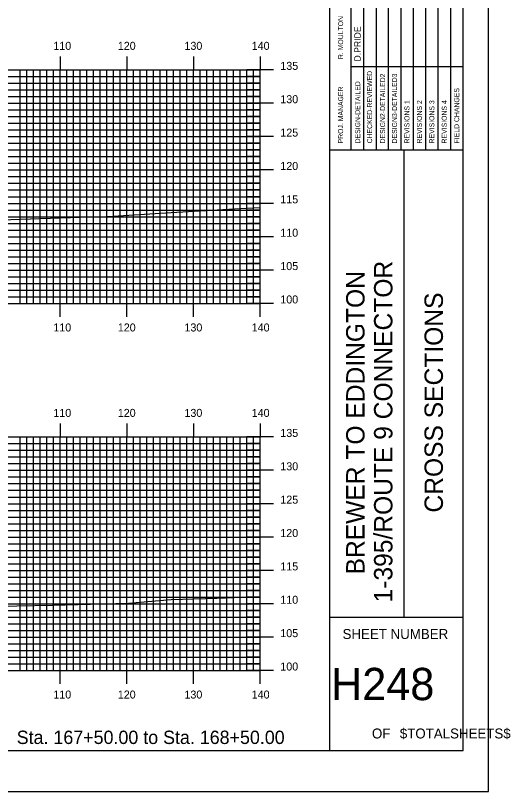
# Model space of a CAD drawing. Extents: x 1781860 to 1782203, y 442591 to 442811.
# Drawn here: x 1782129.2 to 1782203.4, y 442590.5 to 442706.8 of the extents above; entities that cross this region are included whole.
import ezdxf

# ---------------------------------------------------------------- set-up
doc = ezdxf.new("R2010")
doc.units = 0
for name, color, linetype in [('BORDER', 7, 'Continuous'), ('H_V ANNOTATION', 7, 'Continuous'), ('MAJOR', 7, 'Continuous'), ('MINOR', 7, 'Continuous'), ('PLOT BOUNDARY', 7, 'Continuous'), ('S_Roadway_Centerline', 7, 'Continuous')]:
    doc.layers.add(name, color=color, linetype=linetype)

msp = doc.modelspace()

# ---------------------------------------------------------------- linework, layer by layer
at = {"layer": 'BORDER'}
for p, q in [((1782176.32, 442596.67), (1782176.32, 442806.67)), ((1782176.32, 442686.67), (1782196.32, 442686.67)), ((1782187.5, 442616.67), (1782187.5, 442686.67)), ((1782176.32, 442616.67), (1782196.32, 442616.67))]:
    msp.add_line(p, q, dxfattribs=at)
msp.add_lwpolyline([(1781876.32, 442596.67), (1782196.32, 442596.67), (1782196.32, 442806.67), (1781876.32, 442806.67)], close=True, dxfattribs=at)
for points in [[(1782181.42, 442686.68), (1782181.42, 442721.67)], [(1782183.28, 442721.67), (1782183.28, 442686.68)], [(1782185.14, 442686.68), (1782185.14, 442721.67)], [(1782187.01, 442686.68), (1782187.01, 442721.67)], [(1782188.87, 442686.68), (1782188.87, 442721.67)], [(1782190.73, 442686.68), (1782190.73, 442721.67)], [(1782192.6, 442686.68), (1782192.6, 442721.67)], [(1782194.46, 442686.68), (1782194.46, 442721.67)], [(1782179.55, 442686.68), (1782179.55, 442720.26)], [(1782179.55, 442699.17), (1782196.32, 442699.17)]]:
    msp.add_lwpolyline(points, dxfattribs=at)
at = {"layer": 'MAJOR'}
for p, q in [((1782135.92, 442700.67), (1782135.92, 442698.67)), ((1782145.92, 442700.67), (1782145.92, 442698.67)), ((1782155.92, 442700.67), (1782155.92, 442698.67)), ((1782165.92, 442700.67), (1782165.92, 442698.67)), ((1781885.92, 442698.67), (1782165.92, 442698.67)), ((1781885.92, 442698.67), (1782165.92, 442698.67)), ((1782135.92, 442663.67), (1782135.92, 442698.67)), ((1782145.92, 442663.67), (1782145.92, 442698.67)), ((1782155.92, 442663.67), (1782155.92, 442698.67)), ((1782167.92, 442698.67), (1782163.92, 442698.67)), ((1782165.92, 442663.67), (1782165.92, 442698.67)), ((1782165.92, 442663.67), (1782165.92, 442698.67)), ((1781885.92, 442693.67), (1782165.92, 442693.67)), ((1782167.92, 442693.67), (1782163.92, 442693.67)), ((1781885.92, 442688.67), (1782165.92, 442688.67)), ((1782167.92, 442688.67), (1782163.92, 442688.67)), ((1781885.92, 442683.67), (1782165.92, 442683.67)), ((1782167.92, 442683.67), (1782163.92, 442683.67)), ((1781885.92, 442678.67), (1782165.92, 442678.67)), ((1782167.92, 442678.67), (1782163.92, 442678.67)), ((1781885.92, 442673.67), (1782165.92, 442673.67)), ((1782167.92, 442673.67), (1782163.92, 442673.67)), ((1781885.92, 442668.67), (1782165.92, 442668.67)), ((1782167.92, 442668.67), (1782163.92, 442668.67)), ((1781885.92, 442663.67), (1782165.92, 442663.67)), ((1781885.92, 442663.67), (1782165.92, 442663.67)), ((1782135.92, 442661.66), (1782135.92, 442663.67)), ((1782145.92, 442661.66), (1782145.92, 442663.67)), ((1782155.92, 442661.66), (1782155.92, 442663.67)), ((1782167.92, 442663.67), (1782163.92, 442663.67)), ((1782165.92, 442661.66), (1782165.92, 442663.67)), ((1782135.92, 442645.67), (1782135.92, 442643.67)), ((1782145.92, 442645.67), (1782145.92, 442643.67)), ((1782155.92, 442645.67), (1782155.92, 442643.67)), ((1782165.92, 442645.67), (1782165.92, 442643.67)), ((1781885.92, 442643.67), (1782165.92, 442643.67)), ((1781885.92, 442643.67), (1782165.92, 442643.67)), ((1782135.92, 442608.67), (1782135.92, 442643.67)), ((1782145.92, 442608.67), (1782145.92, 442643.67)), ((1782155.92, 442608.67), (1782155.92, 442643.67)), ((1782167.92, 442643.67), (1782163.92, 442643.67)), ((1782165.92, 442608.67), (1782165.92, 442643.67)), ((1782165.92, 442608.67), (1782165.92, 442643.67)), ((1781885.92, 442638.67), (1782165.92, 442638.67)), ((1782167.92, 442638.67), (1782163.92, 442638.67)), ((1781885.92, 442633.67), (1782165.92, 442633.67)), ((1782167.92, 442633.67), (1782163.92, 442633.67)), ((1781885.92, 442628.67), (1782165.92, 442628.67)), ((1782167.92, 442628.67), (1782163.92, 442628.67)), ((1781885.92, 442623.67), (1782165.92, 442623.67)), ((1782167.92, 442623.67), (1782163.92, 442623.67)), ((1781885.92, 442618.67), (1782165.92, 442618.67)), ((1782167.92, 442618.67), (1782163.92, 442618.67)), ((1781885.92, 442613.67), (1782165.92, 442613.67)), ((1782167.92, 442613.67), (1782163.92, 442613.67)), ((1781885.92, 442608.67), (1782165.92, 442608.67)), ((1781885.92, 442608.67), (1782165.92, 442608.67)), ((1782135.92, 442606.66), (1782135.92, 442608.67)), ((1782145.92, 442606.66), (1782145.92, 442608.67)), ((1782155.92, 442606.66), (1782155.92, 442608.67)), ((1782167.92, 442608.67), (1782163.92, 442608.67)), ((1782165.92, 442606.66), (1782165.92, 442608.67))]:
    msp.add_line(p, q, dxfattribs=at)
at = {"layer": 'MINOR'}
for p, q in [((1782129.92, 442663.67), (1782129.92, 442698.67)), ((1782130.92, 442663.67), (1782130.92, 442698.67)), ((1782131.92, 442663.67), (1782131.92, 442698.67)), ((1782132.92, 442663.67), (1782132.92, 442698.67)), ((1782133.92, 442663.67), (1782133.92, 442698.67)), ((1782134.92, 442663.67), (1782134.92, 442698.67)), ((1782136.92, 442663.67), (1782136.92, 442698.67)), ((1782137.92, 442663.67), (1782137.92, 442698.67)), ((1782138.92, 442663.67), (1782138.92, 442698.67)), ((1782139.92, 442663.67), (1782139.92, 442698.67)), ((1782140.92, 442663.67), (1782140.92, 442698.67)), ((1782141.92, 442663.67), (1782141.92, 442698.67)), ((1782142.92, 442663.67), (1782142.92, 442698.67)), ((1782143.92, 442663.67), (1782143.92, 442698.67)), ((1782144.92, 442663.67), (1782144.92, 442698.67)), ((1782146.92, 442663.67), (1782146.92, 442698.67)), ((1782147.92, 442663.67), (1782147.92, 442698.67)), ((1782148.92, 442663.67), (1782148.92, 442698.67)), ((1782149.92, 442663.67), (1782149.92, 442698.67)), ((1782150.92, 442663.67), (1782150.92, 442698.67)), ((1782151.92, 442663.67), (1782151.92, 442698.67)), ((1782152.92, 442663.67), (1782152.92, 442698.67)), ((1782153.92, 442663.67), (1782153.92, 442698.67)), ((1782154.92, 442663.67), (1782154.92, 442698.67)), ((1782156.92, 442663.67), (1782156.92, 442698.67)), ((1782157.92, 442663.67), (1782157.92, 442698.67)), ((1782158.92, 442663.67), (1782158.92, 442698.67)), ((1782159.92, 442663.67), (1782159.92, 442698.67)), ((1782160.92, 442663.67), (1782160.92, 442698.67)), ((1782161.92, 442663.67), (1782161.92, 442698.67)), ((1782162.92, 442663.67), (1782162.92, 442698.67)), ((1782163.92, 442663.67), (1782163.92, 442698.67)), ((1782164.92, 442663.67), (1782164.92, 442698.67)), ((1781885.92, 442697.67), (1782165.92, 442697.67)), ((1782165.92, 442697.67), (1782163.92, 442697.67)), ((1781885.92, 442696.67), (1782165.92, 442696.67)), ((1782165.92, 442696.67), (1782163.92, 442696.67)), ((1781885.92, 442695.67), (1782165.92, 442695.67)), ((1782165.92, 442695.67), (1782163.92, 442695.67)), ((1781885.92, 442694.67), (1782165.92, 442694.67)), ((1782165.92, 442694.67), (1782163.92, 442694.67)), ((1781885.92, 442692.67), (1782165.92, 442692.67)), ((1781885.92, 442691.67), (1782165.92, 442691.67)), ((1782165.92, 442692.67), (1782163.92, 442692.67)), ((1782165.92, 442691.67), (1782163.92, 442691.67)), ((1781885.92, 442690.67), (1782165.92, 442690.67)), ((1782165.92, 442690.67), (1782163.92, 442690.67)), ((1781885.92, 442689.67), (1782165.92, 442689.67)), ((1782165.92, 442689.67), (1782163.92, 442689.67)), ((1781885.92, 442687.67), (1782165.92, 442687.67)), ((1782165.92, 442687.67), (1782163.92, 442687.67)), ((1781885.92, 442686.67), (1782165.92, 442686.67)), ((1782165.92, 442686.67), (1782163.92, 442686.67)), ((1781885.92, 442685.67), (1782165.92, 442685.67)), ((1781885.92, 442684.67), (1782165.92, 442684.67)), ((1782165.92, 442685.67), (1782163.92, 442685.67)), ((1782165.92, 442684.67), (1782163.92, 442684.67)), ((1781885.92, 442682.67), (1782165.92, 442682.67)), ((1782165.92, 442682.67), (1782163.92, 442682.67)), ((1781885.92, 442681.67), (1782165.92, 442681.67)), ((1782165.92, 442681.67), (1782163.92, 442681.67)), ((1781885.92, 442680.67), (1782165.92, 442680.67)), ((1782165.92, 442680.67), (1782163.92, 442680.67)), ((1781885.92, 442679.67), (1782165.92, 442679.67)), ((1782165.92, 442679.67), (1782163.92, 442679.67)), ((1781885.92, 442677.67), (1782165.92, 442677.67)), ((1781885.92, 442676.67), (1782165.92, 442676.67)), ((1782165.92, 442677.67), (1782163.92, 442677.67)), ((1782165.92, 442676.67), (1782163.92, 442676.67)), ((1781885.92, 442675.67), (1782165.92, 442675.67)), ((1782165.92, 442675.67), (1782163.92, 442675.67)), ((1781885.92, 442674.67), (1782165.92, 442674.67)), ((1782165.92, 442674.67), (1782163.92, 442674.67)), ((1781885.92, 442672.67), (1782165.92, 442672.67)), ((1782165.92, 442672.67), (1782163.92, 442672.67)), ((1781885.92, 442671.67), (1782165.92, 442671.67)), ((1782165.92, 442671.67), (1782163.92, 442671.67)), ((1781885.92, 442670.67), (1782165.92, 442670.67)), ((1781885.92, 442669.67), (1782165.92, 442669.67)), ((1782165.92, 442670.67), (1782163.92, 442670.67)), ((1782165.92, 442669.67), (1782163.92, 442669.67)), ((1781885.92, 442667.67), (1782165.92, 442667.67)), ((1782165.92, 442667.67), (1782163.92, 442667.67)), ((1781885.92, 442666.67), (1782165.92, 442666.67)), ((1782165.92, 442666.67), (1782163.92, 442666.67)), ((1781885.92, 442665.67), (1782165.92, 442665.67)), ((1782165.92, 442665.67), (1782163.92, 442665.67)), ((1781885.92, 442664.67), (1782165.92, 442664.67)), ((1782165.92, 442664.67), (1782163.92, 442664.67)), ((1782129.92, 442608.67), (1782129.92, 442643.67)), ((1782130.92, 442608.67), (1782130.92, 442643.67)), ((1782131.92, 442608.67), (1782131.92, 442643.67)), ((1782132.92, 442608.67), (1782132.92, 442643.67)), ((1782133.92, 442608.67), (1782133.92, 442643.67)), ((1782134.92, 442608.67), (1782134.92, 442643.67)), ((1782136.92, 442608.67), (1782136.92, 442643.67)), ((1782137.92, 442608.67), (1782137.92, 442643.67)), ((1782138.92, 442608.67), (1782138.92, 442643.67)), ((1782139.92, 442608.67), (1782139.92, 442643.67)), ((1782140.92, 442608.67), (1782140.92, 442643.67)), ((1782141.92, 442608.67), (1782141.92, 442643.67)), ((1782142.92, 442608.67), (1782142.92, 442643.67)), ((1782143.92, 442608.67), (1782143.92, 442643.67)), ((1782144.92, 442608.67), (1782144.92, 442643.67)), ((1782146.92, 442608.67), (1782146.92, 442643.67)), ((1782147.92, 442608.67), (1782147.92, 442643.67)), ((1782148.92, 442608.67), (1782148.92, 442643.67)), ((1782149.92, 442608.67), (1782149.92, 442643.67)), ((1782150.92, 442608.67), (1782150.92, 442643.67)), ((1782151.92, 442608.67), (1782151.92, 442643.67)), ((1782152.92, 442608.67), (1782152.92, 442643.67)), ((1782153.92, 442608.67), (1782153.92, 442643.67)), ((1782154.92, 442608.67), (1782154.92, 442643.67)), ((1782156.92, 442608.67), (1782156.92, 442643.67)), ((1782157.92, 442608.67), (1782157.92, 442643.67)), ((1782158.92, 442608.67), (1782158.92, 442643.67)), ((1782159.92, 442608.67), (1782159.92, 442643.67)), ((1782160.92, 442608.67), (1782160.92, 442643.67)), ((1782161.92, 442608.67), (1782161.92, 442643.67)), ((1782162.92, 442608.67), (1782162.92, 442643.67)), ((1782163.92, 442608.67), (1782163.92, 442643.67)), ((1782164.92, 442608.67), (1782164.92, 442643.67)), ((1781885.92, 442642.67), (1782165.92, 442642.67)), ((1781885.92, 442641.67), (1782165.92, 442641.67)), ((1782165.92, 442642.67), (1782163.92, 442642.67)), ((1782165.92, 442641.67), (1782163.92, 442641.67)), ((1781885.92, 442640.67), (1782165.92, 442640.67)), ((1782165.92, 442640.67), (1782163.92, 442640.67)), ((1781885.92, 442639.67), (1782165.92, 442639.67)), ((1782165.92, 442639.67), (1782163.92, 442639.67)), ((1781885.92, 442637.67), (1782165.92, 442637.67)), ((1782165.92, 442637.67), (1782163.92, 442637.67)), ((1781885.92, 442636.67), (1782165.92, 442636.67)), ((1782165.92, 442636.67), (1782163.92, 442636.67)), ((1781885.92, 442635.67), (1782165.92, 442635.67)), ((1781885.92, 442634.67), (1782165.92, 442634.67)), ((1782165.92, 442635.67), (1782163.92, 442635.67)), ((1782165.92, 442634.67), (1782163.92, 442634.67)), ((1781885.92, 442632.67), (1782165.92, 442632.67)), ((1782165.92, 442632.67), (1782163.92, 442632.67)), ((1781885.92, 442631.67), (1782165.92, 442631.67)), ((1782165.92, 442631.67), (1782163.92, 442631.67)), ((1781885.92, 442630.67), (1782165.92, 442630.67)), ((1782165.92, 442630.67), (1782163.92, 442630.67)), ((1781885.92, 442629.67), (1782165.92, 442629.67)), ((1782165.92, 442629.67), (1782163.92, 442629.67)), ((1781885.92, 442627.67), (1782165.92, 442627.67)), ((1781885.92, 442626.67), (1782165.92, 442626.67)), ((1782165.92, 442627.67), (1782163.92, 442627.67)), ((1782165.92, 442626.67), (1782163.92, 442626.67)), ((1781885.92, 442625.67), (1782165.92, 442625.67)), ((1782165.92, 442625.67), (1782163.92, 442625.67)), ((1781885.92, 442624.67), (1782165.92, 442624.67)), ((1782165.92, 442624.67), (1782163.92, 442624.67)), ((1781885.92, 442622.67), (1782165.92, 442622.67)), ((1782165.92, 442622.67), (1782163.92, 442622.67)), ((1781885.92, 442621.67), (1782165.92, 442621.67)), ((1782165.92, 442621.67), (1782163.92, 442621.67)), ((1781885.92, 442620.67), (1782165.92, 442620.67)), ((1781885.92, 442619.67), (1782165.92, 442619.67)), ((1782165.92, 442620.67), (1782163.92, 442620.67)), ((1782165.92, 442619.67), (1782163.92, 442619.67)), ((1781885.92, 442617.67), (1782165.92, 442617.67)), ((1782165.92, 442617.67), (1782163.92, 442617.67)), ((1781885.92, 442616.67), (1782165.92, 442616.67)), ((1782165.92, 442616.67), (1782163.92, 442616.67)), ((1781885.92, 442615.67), (1782165.92, 442615.67)), ((1782165.92, 442615.67), (1782163.92, 442615.67)), ((1781885.92, 442614.67), (1782165.92, 442614.67)), ((1782165.92, 442614.67), (1782163.92, 442614.67)), ((1781885.92, 442612.67), (1782165.92, 442612.67)), ((1782165.92, 442612.67), (1782163.92, 442612.67)), ((1781885.92, 442611.67), (1782165.92, 442611.67)), ((1782165.92, 442611.67), (1782163.92, 442611.67)), ((1781885.92, 442610.67), (1782165.92, 442610.67)), ((1782165.92, 442610.67), (1782163.92, 442610.67)), ((1781885.92, 442609.67), (1782165.92, 442609.67)), ((1782165.92, 442609.67), (1782163.92, 442609.67))]:
    msp.add_line(p, q, dxfattribs=at)
at = {"layer": 'PLOT BOUNDARY'}
msp.add_lwpolyline([(1781860.13, 442590.55), (1782200.13, 442590.55), (1782200.13, 442810.55), (1781860.13, 442810.55)], close=True, dxfattribs=at)
at = {"layer": 'S_Roadway_Centerline'}
for points in [[(1782053.31, 442673.39), (1782060.57, 442673.51), (1782069.28, 442674.01), (1782084.58, 442674.76), (1782092.38, 442674.7), (1782099.26, 442674.89), (1782116.6, 442675.76), (1782118.99, 442675.82), (1782120.99, 442675.98), (1782138.96, 442676.59), (1782143, 442676.72), (1782152.54, 442677.3), (1782162.05, 442677.87), (1782165.92, 442678.07)], [(1782055.57, 442617.74), (1782059.11, 442617.89), (1782062.72, 442618.01), (1782071.54, 442618.1), (1782078.18, 442618.06), (1782082.71, 442618.05), (1782087.16, 442617.97), (1782101.99, 442618.18), (1782106.08, 442618.34), (1782110.89, 442618.27), (1782117.6, 442618.17), (1782124.05, 442618.24), (1782134.76, 442618.47), (1782146.14, 442618.76), (1782152.57, 442619.29), (1782159.39, 442619.5), (1782165.92, 442619.75)]]:
    msp.add_lwpolyline(points, dxfattribs=at)

# ---------------------------------------------------------------- texts
at = {"layer": 'BORDER'}
for s, height, p in [('R. MOULTON', 0.745, (1782178.33, 442700.28)), ('D.PRIDE', 0.969, (1782180.97, 442699.92)), ('CHECKED-REVIEWED', 0.7455, (1782182.68, 442687.65)), ('DESIGN2-DETAILED2', 0.7455, (1782184.62, 442687.65)), ('DESIGN3-DETAILED3', 0.7455, (1782186.41, 442687.65)), ('DESIGN-DETAILED', 0.7455, (1782180.89, 442687.65)), ('PROJ. MANAGER', 0.7455, (1782178.33, 442687.65)), ('FIELD CHANGES', 0.7455, (1782195.73, 442687.65)), ('REVISIONS 1', 0.7455, (1782188.27, 442687.65)), ('REVISIONS 2', 0.7455, (1782190.14, 442687.65)), ('REVISIONS 3', 0.7455, (1782192, 442687.65)), ('REVISIONS 4', 0.7455, (1782193.86, 442687.65)), ('1-395/ROUTE 9 CONNECTOR', 2.7557, (1782185.72, 442618.87)), ('BREWER TO EDDINGTON', 2.7557, (1782181.54, 442623.07)), ('CROSS SECTIONS', 2.7557, (1782193.29, 442632.34))]:
    msp.add_text(s, height=height, rotation=90, dxfattribs=at).set_placement(p)
for s, height, p in [('SHEET NUMBER', 1.4905, (1782178.25, 442613.4)), ('H248', 4.839, (1782176.53, 442604.23)), ('OF', 1.491, (1782182.65, 442598.49)), ('$TOTALSHEETS$', 1.4905, (1782186.83, 442598.49))]:
    msp.add_text(s, height=height, dxfattribs=at).set_placement(p)
at = {"layer": 'H_V ANNOTATION'}
for s, height, p in [('110', 1.2, (1782134.9, 442701.67)), ('120', 1.2, (1782144.56, 442701.67)), ('130', 1.2, (1782154.55, 442701.67)), ('140', 1.2, (1782164.63, 442701.67)), ('135', 1.2, (1782168.92, 442698.67)), ('130', 1.2, (1782168.92, 442693.67)), ('125', 1.2, (1782168.92, 442688.67)), ('120', 1.2, (1782168.92, 442683.67)), ('115', 1.2, (1782168.92, 442678.67)), ('110', 1.2, (1782168.92, 442673.67)), ('105', 1.2, (1782168.92, 442668.67)), ('100', 1.2, (1782168.92, 442663.67)), ('110', 1.2, (1782134.9, 442659.47)), ('120', 1.2, (1782144.56, 442659.47)), ('130', 1.2, (1782154.55, 442659.47)), ('140', 1.2, (1782164.63, 442659.47)), ('110', 1.2, (1782134.9, 442646.67)), ('120', 1.2, (1782144.56, 442646.67)), ('130', 1.2, (1782154.55, 442646.67)), ('140', 1.2, (1782164.63, 442646.67)), ('135', 1.2, (1782168.92, 442643.67)), ('130', 1.2, (1782168.92, 442638.67)), ('125', 1.2, (1782168.92, 442633.67)), ('120', 1.2, (1782168.92, 442628.67)), ('115', 1.2, (1782168.92, 442623.67)), ('110', 1.2, (1782168.92, 442618.67)), ('105', 1.2, (1782168.92, 442613.67)), ('100', 1.2, (1782168.92, 442608.67)), ('110', 1.2, (1782134.9, 442604.47)), ('120', 1.2, (1782144.56, 442604.47)), ('130', 1.2, (1782154.55, 442604.47)), ('140', 1.2, (1782164.63, 442604.47)), ('Sta. 167+50.00 to Sta. 168+50.00', 2.0004, (1782129.41, 442597.66))]:
    msp.add_text(s, height=height, dxfattribs=at).set_placement(p)

doc.saveas('drawing.dxf')
